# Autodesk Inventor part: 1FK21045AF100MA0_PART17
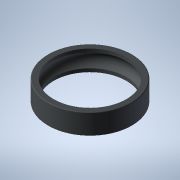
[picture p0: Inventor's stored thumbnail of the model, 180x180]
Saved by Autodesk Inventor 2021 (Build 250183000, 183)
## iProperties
Created: 2025-04
Part Number: 1FK21045AF100MA0_PART17
Material: Generic
Catalog Web Link: www.3dfindit.com
Description: -Servo synchronous motor
Document SubType Name: Modeling
Designer: psAdmin
Mass: 1.64389 g
Surface Area: 26.4305 cm^2
Volume: 1.64389 cm^3
Density: 1 g/cm^3
Appearance: PSOLRGB-212-217-219
Category: PARTsolutions
Title: 1FK21045AF100MA0_PART17
Author: Cadenas PARTsolutions
Comments: Servo synchronous motor
Sending System: PARTsolutions
Preprocessor: ST-DEVELOPER v19.3
PSOL_IDENT_0: {$CADENAS_DATA/23d-libs/siemens_ag/_cat_/52/6b/1fk21045af100ma0.prj},216 {VTYP=3D},{NB=1FK21045AF100
PSOL_IDENT_1: MA0_PART17},{LINA=1FK21045AF100MA0_PART17},{NN=1FK21045AF100MA0_PART17},{NOPRJ=TRUE},{DATE=19.08.202
PSOL_IDENT_2: 5 14:00:38},{GEOMDATE=30.07.2025 02:01:45},{VERSION=},{LINEID=10},{WBVAR=},{WBNUMERIC=}  {NB=1FK2104
PSOL_IDENT_3: 5AF100MA0_PART17},{LINA=1FK21045AF100MA0_PART17},{KT=DUMMY},{PREVIEW=../../../_pool_/cb/72/p_d211_xx
PSOL_IDENT_4: _00434j.png},{DESCSHORT=SIMOTICS S-1FK2 HD, SINAMICS S210 3AC 400V-480V, 2.4 Nm, 3000 rpm},{DESCLONG=
PSOL_IDENT_5: SIMOTICS S-1FK2 HD servo motor M0=2.4 Nm; PN = 0.75 kW at nN=3000 rpm (380-480 V); PN = 0.375 kW at
PSOL_IDENT_6: nN=1500 rpm (200-240 V); with holding brake; degree of protection IP64; cylindrical shaft D19x40mm;
PSOL_IDENT_7: absolute encoder 22-bit + 12-bit multiturn (encoder AM22DQC); with OCC interface; plug size M17, rot
PSOL_IDENT_8: atable; SIMOTICS S-1FK2 servomotorfor a wide range of uses in industrial environments. SIMOTICS S‑1F
PSOL_IDENT_9: K2 servomotors are compact synchronous motors with a high dynamic performance that set themselves ap
PSOL_IDENT_10: art as a result of their high power density, degree of protection and overload capability. The motor
PSOL_IDENT_11: s are available in two variants: as High Dynamic variant (highest dynamic performance as a result of
PSOL_IDENT_12: the low intrinsic moment of inertia for applications demanding a high dynamic performance with low
PSOL_IDENT_13: moved masses) - and as Compact variant (precise and stable closed-loop control for medium up to larg
PSOL_IDENT_14: e moved masses as a result of a medium intrinsic moment of inertia). SIMOTICSS‑1FK2 servomotors full
PSOL_IDENT_15: y exploit their strengths in a system with the SINAMICSS210 frequency converter and simple connectio
PSOL_IDENT_16: n using the one cable connection (OCC). Advantages include the short control and positioning times,
PSOL_IDENT_17: fast and precise correction of disturbing quantities as well as stable control with a high dynamic p
PSOL_IDENT_18: erformance. The servo motors can be configured to address a wide range of requirements. For example
PSOL_IDENT_19: with and without holding brake, IP64 or IP65 degree of protection, singleturn or multiturn absolute
PSOL_IDENT_20: encoders - to name just a few. Further, the servomotors are available in different shaft heights ext
PSOL_IDENT_21: ending from 20 to 100. A shaft sealing ring is available to achieve an IP65 degree of protection and
PSOL_IDENT_22: for subsequent mounting at the motor or as spare part. SIMOTICS - the optimum motor for each and ev
PSOL_IDENT_23: ery motion control application.},{INTNO=804766906411},{SUPPLIERALTNO=1FK2104-5AF10-0MA0},{MANUID=1FK
PSOL_IDENT_24: 21045AF100MA0},{MANUNAME=Siemens},{MANUTYPEDESC=Synchronous motor 1FK2-HD 2.4 NM},{AAU732=SIMOTICS},
PSOL_IDENT_25: {AAO057=S-1FK2},{AAU734=SIMOTICS S-1FK2 HD servo motor M0=2.4 Nm; PN = 0.75 kW at nN=3000 rpm (380-4
PSOL_IDENT_26: 80 V); PN = 0.375 kW at nN=1500 rpm (200-240 V); with holding brake; degree of protection IP64; cyli
PSOL_IDENT_27: ndrical shaft D19x40mm; absolute encoder 22-bit + 12-bit multiturn (encoder AM22DQC); with OCC inter
PSOL_IDENT_28: face; plug size M17, rotatable;},{AAW338=Synchronous motor 1FK2-HD 2.4 NM},{AAO742=SIMOTICS},{AAO663=
PSOL_IDENT_29: 4042948693070},{NOCUPEROU=1},{PRICEQUANTITY=1},{QUANTITYMIN=1},{QUANTITYINT=1},{CTN=85015100},{COO=D
PSOL_IDENT_30: E},{AAO676=1FK2104-5AF10-0MA0},{AAO677=Siemens AG},{ORDERUNIT=C62},{CONTENTUNIT=C62}
NB: 1FK21045AF100MA0_PART17
NT: Servo synchronous motor
NBSYN: $MANUID._PART17
LINA: 1FK21045AF100MA0_PART17
CATALOG: SIEMENS
PREVIEW: ../../../_pool_/cb/72/p_d211_xx_00434j.png
DESCSHORT: SIMOTICS S-1FK2 HD, SINAMICS S210 3AC 400V-480V, 2.4 Nm, 3000 rpm
DESCLONG: SIMOTICS S-1FK2 HD servo motor M0=2.4 Nm; PN = 0.75 kW at nN=3000 rpm (380-480 V); PN = 0.375 kW at nN=1500 rpm (200-240 V); with holding brake; degree of prote
INTNO: 804766906411
SUPPLIERALTNO: 1FK2104-5AF10-0MA0
MANUID: 1FK21045AF100MA0
MANUNAME: Siemens
MANUTYPEDESC: Synchronous motor 1FK2-HD 2.4 NM
AAU732: SIMOTICS
AAO057: S-1FK2
AAU734: SIMOTICS S-1FK2 HD servo motor M0=2.4 Nm; PN = 0.75 kW at nN=3000 rpm (380-480 V); PN = 0.375 kW at nN=1500 rpm (200-240 V); with holding brake; degree of prote
AAW338: Synchronous motor 1FK2-HD 2.4 NM
AAO742: SIMOTICS
AAO663: 4042948693070.0
NOCUPEROU: 1
PRICEQUANTITY: 1
QUANTITYMIN: 1
QUANTITYINT: 1
CTN: 85015100
COO: DE
ARTICLENO: 1FK21045AF100MA0_PART17
BOMINFO: 1FK21045AF100MA0_PART17
CREATOR: CADENAS GmbH
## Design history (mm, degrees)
feature "2025_04_17_15_34_52_0317"
body "Solid1"
